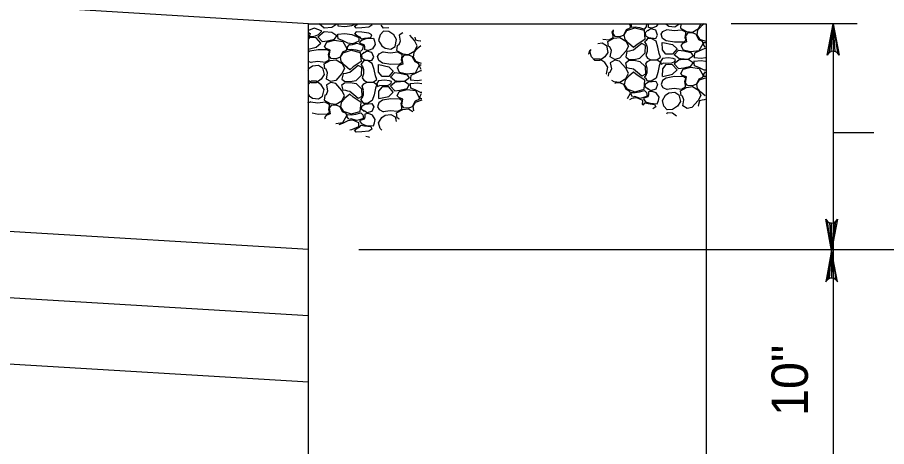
# Model space of a CAD drawing. Extents: x -0.97 to 5.98, y -2.63 to 7.27.
# Drawn here: x 3.389 to 4.822, y 5.158 to 5.867 of the extents above; entities that cross this region are included whole.
import ezdxf

# ---------------------------------------------------------------- set-up
doc = ezdxf.new("R2010")
doc.units = 0
for name, color, linetype in [('DETL-DIMS', 7, 'Continuous'), ('DETL-LINE', 7, 'Continuous'), ('DETL-NOTE', 7, 'Continuous'), ('DETL-PATT', 7, 'Continuous')]:
    doc.layers.add(name, color=color, linetype=linetype)

msp = doc.modelspace()

# ---------------------------------------------------------------- linework, layer by layer
at = {"layer": 'DETL-DIMS'}
for p, q in [((4.7733, 5.8562), (4.5658, 5.8562)), ((4.7339, 5.8562), (4.7339, 4.6209)), ((4.7339, 5.6768), (4.801, 5.6768)), ((3.952, 5.4834), (5.0535, 5.4834))]:
    msp.add_line(p, q, dxfattribs=at)
for points in [[(4.7339, 5.8562), (4.7436, 5.8044), (4.7408, 5.8084), (4.7373, 5.8104), (4.7339, 5.811), (4.7304, 5.8104), (4.7269, 5.8084), (4.7242, 5.8044), (4.7339, 5.8562), (4.7269, 5.8084), (4.7304, 5.8104), (4.7339, 5.8562), (4.7339, 5.811), (4.7373, 5.8104), (4.7339, 5.8562), (4.7408, 5.8084)], [(4.7339, 5.8562), (4.7436, 5.8044), (4.7408, 5.8084), (4.7373, 5.8104), (4.7339, 5.811), (4.7304, 5.8104), (4.7269, 5.8084), (4.7242, 5.8044), (4.7339, 5.8562), (4.7269, 5.8084), (4.7304, 5.8104), (4.7339, 5.8562), (4.7339, 5.811), (4.7373, 5.8104), (4.7339, 5.8562), (4.7408, 5.8084)], [(4.7312, 5.4821), (4.7215, 5.5339), (4.7243, 5.5299), (4.7278, 5.5279), (4.7312, 5.5273), (4.7347, 5.5279), (4.7382, 5.5299), (4.7409, 5.5339), (4.7312, 5.4821), (4.7382, 5.5299), (4.7347, 5.5279), (4.7312, 5.4821), (4.7312, 5.5273), (4.7278, 5.5279), (4.7312, 5.4821), (4.7243, 5.5299)], [(4.7312, 5.4821), (4.7215, 5.4304), (4.7243, 5.4344), (4.7278, 5.4364), (4.7312, 5.437), (4.7347, 5.4364), (4.7382, 5.4344), (4.7409, 5.4304), (4.7312, 5.4821), (4.7382, 5.4344), (4.7347, 5.4364), (4.7312, 5.4821), (4.7312, 5.437), (4.7278, 5.4364), (4.7312, 5.4821), (4.7243, 5.4344)]]:
    msp.add_lwpolyline(points, dxfattribs=at)
at = {"layer": 'DETL-LINE'}
for p, q in [((3.8687, 5.8562), (-0.0802, 6.0971)), ((3.8687, 5.8562), (4.5242, 5.8562)), ((3.8687, 4.6209), (3.8687, 5.8562)), ((4.5242, 5.8562), (4.5242, 4.6209)), ((3.8687, 5.4834), (-0.0802, 5.7244)), ((3.8687, 5.3739), (-0.0802, 5.6149)), ((3.8687, 5.2644), (-0.0802, 5.5053))]:
    msp.add_line(p, q, dxfattribs=at)
at = {"layer": 'DETL-PATT'}
for points in [[(3.8697, 5.8356), (3.875, 5.8356), (3.8805, 5.8362), (3.8854, 5.8388), (3.8906, 5.8443), (3.886, 5.8466), (3.8779, 5.8489), (3.8686, 5.845)], [(3.9153, 5.8557), (3.9153, 5.8556), (3.9075, 5.8501), (3.8944, 5.8492), (3.8863, 5.856)], [(3.9174, 5.8557), (3.9174, 5.8556), (3.9171, 5.8542), (3.9174, 5.8527)], [(3.9174, 5.853), (3.9287, 5.8518), (3.94, 5.8536), (3.9446, 5.8554)], [(3.9729, 5.8551), (3.9734, 5.8542), (3.9685, 5.851), (3.9569, 5.8495), (3.9476, 5.8489), (3.9444, 5.8521), (3.947, 5.8527), (3.947, 5.8539)], [(3.9458, 5.8533), (3.9495, 5.8554)], [(4.001, 5.8495), (4.001, 5.8495), (3.9926, 5.8492), (3.9884, 5.8539)], [(4.3976, 5.8562), (4.3997, 5.8523), (4.3988, 5.8491), (4.3928, 5.8462), (4.3887, 5.8381)], [(4.3964, 5.8244), (4.3907, 5.8306), (4.3893, 5.8381), (4.3936, 5.8451), (4.407, 5.8497), (4.4221, 5.8457), (4.4235, 5.8306), (4.4105, 5.8222), (4.4049, 5.8172), (4.3962, 5.8245)], [(4.4016, 5.8562), (4.4006, 5.8544), (4.4006, 5.8509), (4.4076, 5.8512), (4.4145, 5.85), (4.423, 5.8477), (4.4261, 5.8512), (4.4269, 5.8562)], [(4.4285, 5.8457), (4.4241, 5.8416), (4.4244, 5.8367), (4.4293, 5.8335), (4.4413, 5.8323), (4.4442, 5.8378), (4.4413, 5.8457), (4.4325, 5.848), (4.4288, 5.8448)], [(4.4451, 5.8562), (4.4421, 5.8518), (4.4354, 5.8491), (4.4296, 5.85), (4.4296, 5.8549), (4.4292, 5.8562)], [(4.4582, 5.8562), (4.463, 5.8526), (4.4726, 5.8515), (4.4796, 5.8558), (4.4797, 5.8562)], [(4.4829, 5.8562), (4.4819, 5.8491), (4.4921, 5.8436), (4.5017, 5.8425), (4.5118, 5.8486), (4.5155, 5.8562)], [(4.5161, 5.8519), (4.5104, 5.8457), (4.5089, 5.8381), (4.5133, 5.8312), (4.5239, 5.8275)], [(4.5212, 5.8562), (4.5159, 5.8518)], [(3.8684, 5.8146), (3.8813, 5.8176), (3.8889, 5.8246), (3.8813, 5.8333), (3.8703, 5.8336), (3.8685, 5.8312)], [(3.8686, 5.8422), (3.8715, 5.8402), (3.8697, 5.835), (3.8685, 5.8354)], [(3.8843, 5.8347), (3.8912, 5.8269), (3.8999, 5.8281), (3.9118, 5.8307), (3.9153, 5.8365), (3.9075, 5.842), (3.8944, 5.8429), (3.8843, 5.8344)], [(3.9174, 5.8391), (3.9287, 5.8402), (3.94, 5.8385), (3.9516, 5.8339), (3.9519, 5.8275), (3.942, 5.8231), (3.9339, 5.8243), (3.9249, 5.8286), (3.9176, 5.8315), (3.9174, 5.8365), (3.9171, 5.8379), (3.9174, 5.8394)], [(3.9458, 5.8388), (3.9531, 5.8347), (3.9557, 5.8315), (3.9612, 5.8324), (3.9714, 5.8339), (3.9734, 5.8379), (3.9685, 5.8411), (3.9569, 5.8426), (3.9476, 5.8431), (3.9444, 5.84), (3.947, 5.8394), (3.947, 5.8382)], [(3.9897, 5.8199), (3.9952, 5.8159), (4.0048, 5.8147), (4.0117, 5.8191), (4.0141, 5.8304), (4.0094, 5.8379), (4.001, 5.8437), (3.9926, 5.844), (3.9871, 5.8379), (3.9844, 5.8289), (3.9897, 5.8199)], [(4.0151, 5.8204), (4.0141, 5.8124), (4.0242, 5.8069), (4.0338, 5.8057), (4.044, 5.8118), (4.048, 5.8202), (4.0437, 5.8286), (4.0356, 5.8376)], [(4.0245, 5.8414), (4.0181, 5.8376), (4.0199, 5.8275), (4.0176, 5.8214), (4.0146, 5.8202)], [(4.0498, 5.8284), (4.0457, 5.8292), (4.0444, 5.8345)], [(4.354, 5.8309), (4.3643, 5.8297), (4.371, 5.8335), (4.371, 5.8364), (4.3695, 5.8425), (4.3706, 5.8454)], [(4.3633, 5.8191), (4.3623, 5.8271), (4.3724, 5.8326), (4.382, 5.8338), (4.3922, 5.8277), (4.3962, 5.8193), (4.3919, 5.8109), (4.3814, 5.7993), (4.3736, 5.7975), (4.3663, 5.8019), (4.3681, 5.812), (4.3657, 5.8181), (4.3628, 5.8193)], [(4.3893, 5.8378), (4.3817, 5.8349), (4.3742, 5.8355), (4.371, 5.8402), (4.3719, 5.8465)], [(4.4597, 5.8468), (4.4715, 5.8451), (4.4839, 5.8465), (4.4906, 5.8428), (4.4906, 5.8399), (4.4892, 5.8338), (4.4909, 5.8291), (4.4874, 5.8262), (4.4723, 5.8259), (4.4587, 5.8283), (4.4526, 5.8323), (4.4505, 5.839), (4.4532, 5.8436), (4.4604, 5.8471)], [(4.5089, 5.8384), (4.5014, 5.8413), (4.4938, 5.8407), (4.4906, 5.8361), (4.4921, 5.8265), (4.4854, 5.8239), (4.4828, 5.8207), (4.4863, 5.8135), (4.4993, 5.8103), (4.513, 5.8123), (4.5194, 5.8239), (4.5185, 5.8271), (4.5124, 5.83), (4.5083, 5.8381)], [(3.9214, 5.8011), (3.9139, 5.7982), (3.9063, 5.7988), (3.9031, 5.8034), (3.9046, 5.813), (3.8979, 5.8156), (3.8953, 5.8188), (3.8988, 5.826), (3.9118, 5.8292), (3.9255, 5.8272), (3.9319, 5.8156), (3.931, 5.8124), (3.9249, 5.8095), (3.9208, 5.8014)], [(3.9351, 5.8217), (3.9327, 5.8176), (3.9327, 5.8141), (3.9397, 5.8144), (3.9467, 5.8133), (3.9551, 5.811), (3.9583, 5.8144), (3.9592, 5.8202), (3.9531, 5.8226), (3.9479, 5.824), (3.9391, 5.8211), (3.9359, 5.8223)], [(3.9531, 5.8249), (3.9566, 5.8295), (3.9641, 5.8318), (3.9757, 5.8327), (3.9778, 5.8275), (3.9789, 5.822), (3.9743, 5.815), (3.9676, 5.8124), (3.9618, 5.8133), (3.9618, 5.8182), (3.9606, 5.8217), (3.954, 5.8237), (3.9534, 5.8246)], [(4.054, 5.82), (4.048, 5.815)], [(4.0539, 5.8274), (4.0536, 5.8275), (4.0498, 5.8284)], [(4.346, 5.8239), (4.353, 5.8248), (4.3599, 5.8204), (4.3623, 5.8091), (4.3576, 5.8016), (4.3492, 5.7958), (4.3408, 5.7955), (4.3352, 5.8016), (4.3326, 5.8106), (4.3347, 5.8141)], [(4.398, 5.8112), (4.3939, 5.8103), (4.3919, 5.8019), (4.3962, 5.7981), (4.4055, 5.7975), (4.4151, 5.7996), (4.4238, 5.8083), (4.4247, 5.8207), (4.4186, 5.8239), (4.4113, 5.8181), (4.4049, 5.8126), (4.4018, 5.812), (4.398, 5.8112)], [(4.427, 5.8106), (4.425, 5.8039), (4.4279, 5.7998), (4.4334, 5.7969), (4.4433, 5.7967), (4.4494, 5.801), (4.4471, 5.8071), (4.4447, 5.8178), (4.4418, 5.8274), (4.4337, 5.8323), (4.4276, 5.8323), (4.4253, 5.8286), (4.4227, 5.8259), (4.4256, 5.8225), (4.4273, 5.8178), (4.427, 5.8109)], [(4.4529, 5.8257), (4.4688, 5.8219), (4.4764, 5.8149), (4.4688, 5.8062), (4.4578, 5.8059), (4.4523, 5.8132), (4.452, 5.8257)], [(4.5226, 5.8178), (4.5202, 5.8219), (4.5202, 5.8254), (4.5238, 5.8252)], [(3.8722, 5.7927), (3.884, 5.7944), (3.8964, 5.793), (3.9031, 5.7967), (3.9031, 5.7996), (3.9017, 5.8057), (3.9034, 5.8104), (3.8999, 5.8133), (3.8848, 5.8136), (3.8712, 5.8112), (3.8684, 5.8094)], [(3.9286, 5.7876), (3.9229, 5.7938), (3.9214, 5.8014), (3.9258, 5.8083), (3.9391, 5.813), (3.9542, 5.8089), (3.9557, 5.7938), (3.9426, 5.7854), (3.9371, 5.7805), (3.9284, 5.7878)], [(3.9606, 5.8089), (3.9563, 5.8049), (3.9566, 5.7999), (3.9615, 5.7967), (3.9734, 5.7956), (3.9763, 5.8011), (3.9734, 5.8089), (3.9647, 5.8112), (3.9609, 5.8081)], [(3.9919, 5.81), (4.0036, 5.8083), (4.0161, 5.8098), (4.0228, 5.806), (4.0228, 5.8031), (4.0213, 5.797), (4.0231, 5.7924), (4.0196, 5.7895), (4.0045, 5.7892), (3.9908, 5.7915), (3.9847, 5.7956), (3.9827, 5.8023), (3.9853, 5.8069), (3.9926, 5.8104)], [(4.0411, 5.8017), (4.0335, 5.8046), (4.026, 5.804), (4.0228, 5.7994), (4.0242, 5.7898), (4.0176, 5.7872), (4.0149, 5.784), (4.0184, 5.7767), (4.0315, 5.7735), (4.0451, 5.7756), (4.0515, 5.7872), (4.0507, 5.7904), (4.0446, 5.7933), (4.0405, 5.8014)], [(4.0482, 5.8152), (4.0425, 5.8089), (4.0411, 5.8014), (4.0454, 5.7944), (4.0547, 5.7912)], [(4.3303, 5.8068), (4.3309, 5.8068), (4.3329, 5.812), (4.3331, 5.8127)], [(4.4717, 5.8048), (4.4787, 5.8126), (4.4874, 5.8114), (4.4993, 5.8088), (4.5028, 5.803), (4.495, 5.7975), (4.4819, 5.7967), (4.4717, 5.8051)], [(4.5237, 5.8155), (4.5214, 5.8152), (4.5124, 5.8109), (4.5051, 5.808), (4.5049, 5.803), (4.5046, 5.8016), (4.5049, 5.8001)], [(4.5238, 5.8174), (4.5234, 5.8172)], [(3.8683, 5.7946), (3.8729, 5.7924)], [(3.8955, 5.7823), (3.8944, 5.7904), (3.9046, 5.7959), (3.9142, 5.797), (3.9243, 5.7909), (3.9284, 5.7825), (3.924, 5.7741), (3.9136, 5.7625), (3.9057, 5.7608), (3.8985, 5.7651), (3.9002, 5.7753), (3.8979, 5.7814), (3.895, 5.7825)], [(3.9592, 5.7738), (3.9571, 5.7672), (3.96, 5.7631), (3.9656, 5.7602), (3.9754, 5.7599), (3.9815, 5.7643), (3.9792, 5.7704), (3.9769, 5.7811), (3.974, 5.7907), (3.9659, 5.7956), (3.9598, 5.7956), (3.9574, 5.7918), (3.9548, 5.7892), (3.9577, 5.7857), (3.9595, 5.7811), (3.9592, 5.7741)], [(4.3597, 5.7733), (4.3599, 5.7735), (4.3623, 5.7848), (4.3576, 5.7923), (4.3492, 5.7981), (4.3408, 5.7984), (4.3392, 5.7967)], [(4.3683, 5.7635), (4.3724, 5.7613), (4.382, 5.7601), (4.3922, 5.7662), (4.3962, 5.7746), (4.3919, 5.783), (4.3814, 5.7946), (4.3736, 5.7964), (4.3663, 5.792), (4.3681, 5.7819), (4.3657, 5.7758), (4.3628, 5.7746)], [(4.398, 5.7827), (4.3939, 5.7836), (4.3919, 5.792), (4.3962, 5.7958), (4.4055, 5.7964), (4.4151, 5.7943), (4.4238, 5.7856), (4.4247, 5.7732), (4.4186, 5.77), (4.4113, 5.7758), (4.4049, 5.7813), (4.4018, 5.7819), (4.398, 5.7827)], [(4.427, 5.7833), (4.425, 5.79), (4.4279, 5.794), (4.4334, 5.7969), (4.4433, 5.7972), (4.4494, 5.7929), (4.4471, 5.7868), (4.4447, 5.7761), (4.4418, 5.7665), (4.4337, 5.7616), (4.4276, 5.7616), (4.4253, 5.7653), (4.4227, 5.7679), (4.4256, 5.7714), (4.4273, 5.7761), (4.427, 5.783)], [(4.4534, 5.7917), (4.4625, 5.7911), (4.468, 5.7917), (4.4729, 5.7943), (4.4738, 5.7975), (4.47, 5.799), (4.4619, 5.8001), (4.4523, 5.799), (4.4494, 5.7943), (4.4505, 5.7894), (4.4532, 5.7906), (4.4537, 5.7917)], [(4.4717, 5.7903), (4.4787, 5.7824), (4.4874, 5.7836), (4.4993, 5.7862), (4.5028, 5.792), (4.495, 5.7975), (4.4819, 5.7984), (4.4717, 5.79)], [(4.5234, 5.7796), (4.5214, 5.7798), (4.5124, 5.7842), (4.5051, 5.7871), (4.5049, 5.792), (4.5046, 5.7935), (4.5049, 5.7949)], [(4.5049, 5.8004), (4.5162, 5.7993), (4.5236, 5.8004)], [(4.5049, 5.7946), (4.5162, 5.7958), (4.5235, 5.7947)], [(3.87, 5.7828), (3.8755, 5.7869), (3.8851, 5.788), (3.8921, 5.7837), (3.8944, 5.7724), (3.8898, 5.7648), (3.8813, 5.759), (3.8729, 5.7588), (3.8681, 5.764)], [(3.8682, 5.7797), (3.87, 5.7828)], [(3.9301, 5.7744), (3.9261, 5.7735), (3.924, 5.7651), (3.9284, 5.7614), (3.9377, 5.7608), (3.9473, 5.7628), (3.956, 5.7715), (3.9569, 5.784), (3.9508, 5.7872), (3.9435, 5.7814), (3.9371, 5.7759), (3.9339, 5.7753), (3.9301, 5.7744)], [(3.985, 5.7889), (4.001, 5.7851), (4.0085, 5.7782), (4.001, 5.7695), (3.99, 5.7692), (3.9844, 5.7764), (3.9842, 5.7889)], [(4.0039, 5.768), (4.0109, 5.7759), (4.0196, 5.7747), (4.0315, 5.7721), (4.035, 5.7663), (4.0271, 5.7608), (4.0141, 5.7599), (4.0039, 5.7683)], [(4.0549, 5.7787), (4.0536, 5.7785), (4.0446, 5.7741), (4.0373, 5.7712), (4.037, 5.7663), (4.0367, 5.7648), (4.037, 5.7634)], [(4.0547, 5.7811), (4.0524, 5.7851), (4.0524, 5.7886), (4.0547, 5.7885)], [(4.3964, 5.7695), (4.3907, 5.7633), (4.3893, 5.7558), (4.3936, 5.7488), (4.407, 5.7442), (4.4221, 5.7482), (4.4235, 5.7633), (4.4105, 5.7717), (4.4049, 5.7766), (4.3962, 5.7694)], [(4.4529, 5.7694), (4.4688, 5.7732), (4.4764, 5.7801), (4.4688, 5.7888), (4.4578, 5.7891), (4.4523, 5.7819), (4.452, 5.7694)], [(4.5089, 5.7566), (4.5014, 5.7537), (4.4938, 5.7543), (4.4906, 5.759), (4.4921, 5.7685), (4.4854, 5.7711), (4.4828, 5.7743), (4.4863, 5.7816), (4.4993, 5.7848), (4.513, 5.7827), (4.5194, 5.7711), (4.5185, 5.7679), (4.5124, 5.765), (4.5083, 5.7569)], [(4.5226, 5.7772), (4.5202, 5.7732), (4.5202, 5.7697), (4.5233, 5.7698)], [(3.87, 5.7376), (3.8755, 5.7335), (3.8851, 5.7324), (3.8921, 5.7367), (3.8944, 5.748), (3.8898, 5.7556), (3.8813, 5.7614), (3.8729, 5.7617), (3.8681, 5.7563)], [(3.9856, 5.755), (3.9946, 5.7544), (4.0001, 5.755), (4.0051, 5.7576), (4.0059, 5.7608), (4.0022, 5.7622), (3.994, 5.7634), (3.9844, 5.7622), (3.9815, 5.7576), (3.9827, 5.7527), (3.9853, 5.7538), (3.9859, 5.755)], [(4.0039, 5.7535), (4.0109, 5.7457), (4.0196, 5.7469), (4.0315, 5.7495), (4.035, 5.7553), (4.0271, 5.7608), (4.0141, 5.7617), (4.0039, 5.7532)], [(4.037, 5.7637), (4.0483, 5.7625), (4.0552, 5.7636)], [(4.3633, 5.7748), (4.3627, 5.7699)], [(4.4285, 5.7482), (4.4241, 5.7523), (4.4244, 5.7572), (4.4293, 5.7604), (4.4413, 5.7616), (4.4442, 5.7561), (4.4413, 5.7482), (4.4325, 5.7459), (4.4288, 5.7491)], [(4.4597, 5.7483), (4.4715, 5.75), (4.4839, 5.7485), (4.4906, 5.7523), (4.4906, 5.7552), (4.4892, 5.7613), (4.4909, 5.7659), (4.4874, 5.7688), (4.4723, 5.7691), (4.4587, 5.7668), (4.4526, 5.7627), (4.4505, 5.7561), (4.4532, 5.7514), (4.4604, 5.7479)], [(4.5161, 5.7431), (4.5104, 5.7494), (4.5089, 5.7569), (4.5133, 5.7639), (4.5232, 5.7673)], [(3.8955, 5.7381), (3.8944, 5.73), (3.9046, 5.7245), (3.9142, 5.7234), (3.9243, 5.7295), (3.9284, 5.7379), (3.924, 5.7463), (3.9136, 5.7579), (3.9057, 5.7596), (3.8985, 5.7553), (3.9002, 5.7451), (3.8979, 5.739), (3.895, 5.7379)], [(3.9301, 5.746), (3.9261, 5.7469), (3.924, 5.7553), (3.9284, 5.759), (3.9377, 5.7596), (3.9473, 5.7576), (3.956, 5.7489), (3.9569, 5.7364), (3.9508, 5.7332), (3.9435, 5.739), (3.9371, 5.7445), (3.9339, 5.7451), (3.9301, 5.746)], [(3.9592, 5.7466), (3.9571, 5.7532), (3.96, 5.7573), (3.9656, 5.7602), (3.9754, 5.7605), (3.9815, 5.7561), (3.9792, 5.7501), (3.9769, 5.7393), (3.974, 5.7298), (3.9659, 5.7248), (3.9598, 5.7248), (3.9574, 5.7286), (3.9548, 5.7312), (3.9577, 5.7347), (3.9595, 5.7393), (3.9592, 5.7463)], [(3.985, 5.7327), (4.001, 5.7364), (4.0085, 5.7434), (4.001, 5.7521), (3.99, 5.7524), (3.9844, 5.7451), (3.9842, 5.7327)], [(4.0411, 5.7199), (4.0335, 5.717), (4.026, 5.7176), (4.0228, 5.7222), (4.0242, 5.7318), (4.0176, 5.7344), (4.0149, 5.7376), (4.0184, 5.7448), (4.0315, 5.748), (4.0451, 5.746), (4.0515, 5.7344), (4.0507, 5.7312), (4.0446, 5.7283), (4.0405, 5.7202)], [(4.0557, 5.7428), (4.0536, 5.7431), (4.0446, 5.7474), (4.0373, 5.7503), (4.037, 5.7553), (4.0367, 5.7567), (4.037, 5.7582)], [(4.037, 5.7579), (4.0483, 5.759), (4.0554, 5.758)], [(4.3893, 5.7561), (4.3817, 5.759), (4.3742, 5.7584), (4.3736, 5.7575)], [(4.395, 5.733), (4.3997, 5.7416), (4.3988, 5.7447), (4.3928, 5.7476), (4.3887, 5.7558)], [(4.483, 5.7379), (4.4819, 5.7459), (4.4921, 5.7514), (4.5017, 5.7526), (4.5118, 5.7465), (4.5159, 5.7381), (4.5115, 5.7297), (4.5011, 5.7181), (4.4932, 5.7163), (4.486, 5.7207), (4.4877, 5.7308), (4.4854, 5.7369), (4.4825, 5.7381)], [(3.868, 5.7411), (3.87, 5.7376)], [(3.9286, 5.7328), (3.9229, 5.7266), (3.9214, 5.719), (3.9258, 5.7121), (3.9391, 5.7074), (3.9542, 5.7115), (3.9557, 5.7266), (3.9426, 5.735), (3.9371, 5.7399), (3.9284, 5.7327)], [(4.0547, 5.7405), (4.0524, 5.7364), (4.0524, 5.7329), (4.0559, 5.7331)], [(4.0557, 5.741), (4.0556, 5.7411)], [(4.4187, 5.723), (4.4195, 5.7233), (4.4198, 5.7297), (4.4099, 5.734), (4.4018, 5.7329), (4.398, 5.731)], [(4.4029, 5.7355), (4.4006, 5.7395), (4.4006, 5.743), (4.4076, 5.7427), (4.4145, 5.7439), (4.423, 5.7462), (4.4261, 5.7427), (4.427, 5.7369), (4.4209, 5.7346), (4.4157, 5.7331), (4.407, 5.736), (4.4038, 5.7349)], [(4.4209, 5.7323), (4.4244, 5.7276), (4.432, 5.7253), (4.4436, 5.7244), (4.4456, 5.7297), (4.4468, 5.7352), (4.4421, 5.7421), (4.4354, 5.7447), (4.4296, 5.7439), (4.4296, 5.7389), (4.4285, 5.7355), (4.4218, 5.7334), (4.4212, 5.7326)], [(4.4575, 5.7384), (4.463, 5.7424), (4.4726, 5.7436), (4.4796, 5.7392), (4.4819, 5.7279), (4.4773, 5.7204), (4.4688, 5.7146), (4.4604, 5.7143), (4.4549, 5.7204), (4.4523, 5.7294), (4.4575, 5.7384)], [(4.5229, 5.7374), (4.5159, 5.7433)], [(3.8679, 5.7256), (3.8729, 5.728)], [(3.8722, 5.7277), (3.884, 5.726), (3.8964, 5.7274), (3.9031, 5.7237), (3.9031, 5.7208), (3.9017, 5.7147), (3.9034, 5.71), (3.8999, 5.7071), (3.8848, 5.7068), (3.875, 5.7085)], [(3.9214, 5.7193), (3.9139, 5.7222), (3.9063, 5.7216), (3.9031, 5.717), (3.9046, 5.7074), (3.8979, 5.7048), (3.8953, 5.7016), (3.8965, 5.6992)], [(3.914, 5.6915), (3.9255, 5.6932), (3.9319, 5.7048), (3.931, 5.708), (3.9249, 5.7109), (3.9208, 5.719)], [(3.9606, 5.7115), (3.9563, 5.7155), (3.9566, 5.7205), (3.9615, 5.7237), (3.9734, 5.7248), (3.9763, 5.7193), (3.9734, 5.7115), (3.9647, 5.7092), (3.9609, 5.7124)], [(3.9919, 5.7115), (4.0036, 5.7132), (4.0161, 5.7118), (4.0228, 5.7155), (4.0228, 5.7184), (4.0213, 5.7245), (4.0231, 5.7292), (4.0196, 5.7321), (4.0045, 5.7324), (3.9908, 5.73), (3.9847, 5.726), (3.9827, 5.7193), (3.9853, 5.7147), (3.9926, 5.7112)], [(4.0425, 5.7128), (4.0411, 5.7202), (4.0454, 5.7271), (4.056, 5.7308)], [(4.4206, 5.7222), (4.4209, 5.7224), (4.4235, 5.7256), (4.4291, 5.7247), (4.4392, 5.7233), (4.4413, 5.7192), (4.4363, 5.716)], [(4.5176, 5.73), (4.5136, 5.7291), (4.5115, 5.7207), (4.5116, 5.7206)], [(4.5229, 5.7311), (4.5214, 5.7308), (4.5176, 5.73)], [(3.9351, 5.6987), (3.9327, 5.7028), (3.9327, 5.7063), (3.9397, 5.706), (3.9467, 5.7071), (3.9551, 5.7095), (3.9583, 5.706), (3.9592, 5.7002), (3.9531, 5.6979), (3.9479, 5.6964), (3.9391, 5.6993), (3.9359, 5.6981)], [(3.9531, 5.6955), (3.9566, 5.6909), (3.9641, 5.6886), (3.9757, 5.6877), (3.9778, 5.6929), (3.9789, 5.6984), (3.9743, 5.7054), (3.9676, 5.708), (3.9618, 5.7071), (3.9618, 5.7022), (3.9606, 5.6987), (3.954, 5.6967), (3.9534, 5.6958)], [(3.9897, 5.7016), (3.9952, 5.7057), (4.0048, 5.7068), (4.0117, 5.7025), (4.0133, 5.695)], [(4.0151, 5.7011), (4.0141, 5.7092), (4.0242, 5.7147), (4.0338, 5.7158), (4.0407, 5.7117)], [(4.4758, 5.704), (4.4688, 5.7088), (4.4604, 5.7091), (4.4588, 5.7073)], [(3.9371, 5.6815), (3.94, 5.6819), (3.9516, 5.6865), (3.9519, 5.6929), (3.942, 5.6973), (3.9339, 5.6961), (3.9249, 5.6918), (3.9189, 5.6894)], [(3.9897, 5.6807), (3.9871, 5.6836), (3.9844, 5.6926), (3.9897, 5.7016)], [(4.0183, 5.6981), (4.0176, 5.7002), (4.0146, 5.7013)], [(3.9458, 5.6816), (3.9531, 5.6857), (3.9557, 5.6889), (3.9612, 5.688), (3.9714, 5.6865), (3.9734, 5.6825), (3.9685, 5.6793), (3.9569, 5.6778), (3.9476, 5.6773), (3.9444, 5.6805), (3.947, 5.681), (3.947, 5.6822)], [(3.9698, 5.6686), (3.9685, 5.6694), (3.9632, 5.6701)]]:
    msp.add_lwpolyline(points, dxfattribs=at)

# ---------------------------------------------------------------- texts
at = {"layer": 'DETL-NOTE'}
msp.add_text('10"', height=0.06, rotation=90, dxfattribs=at).set_placement((4.6922, 5.2086))

doc.saveas('drawing.dxf')
